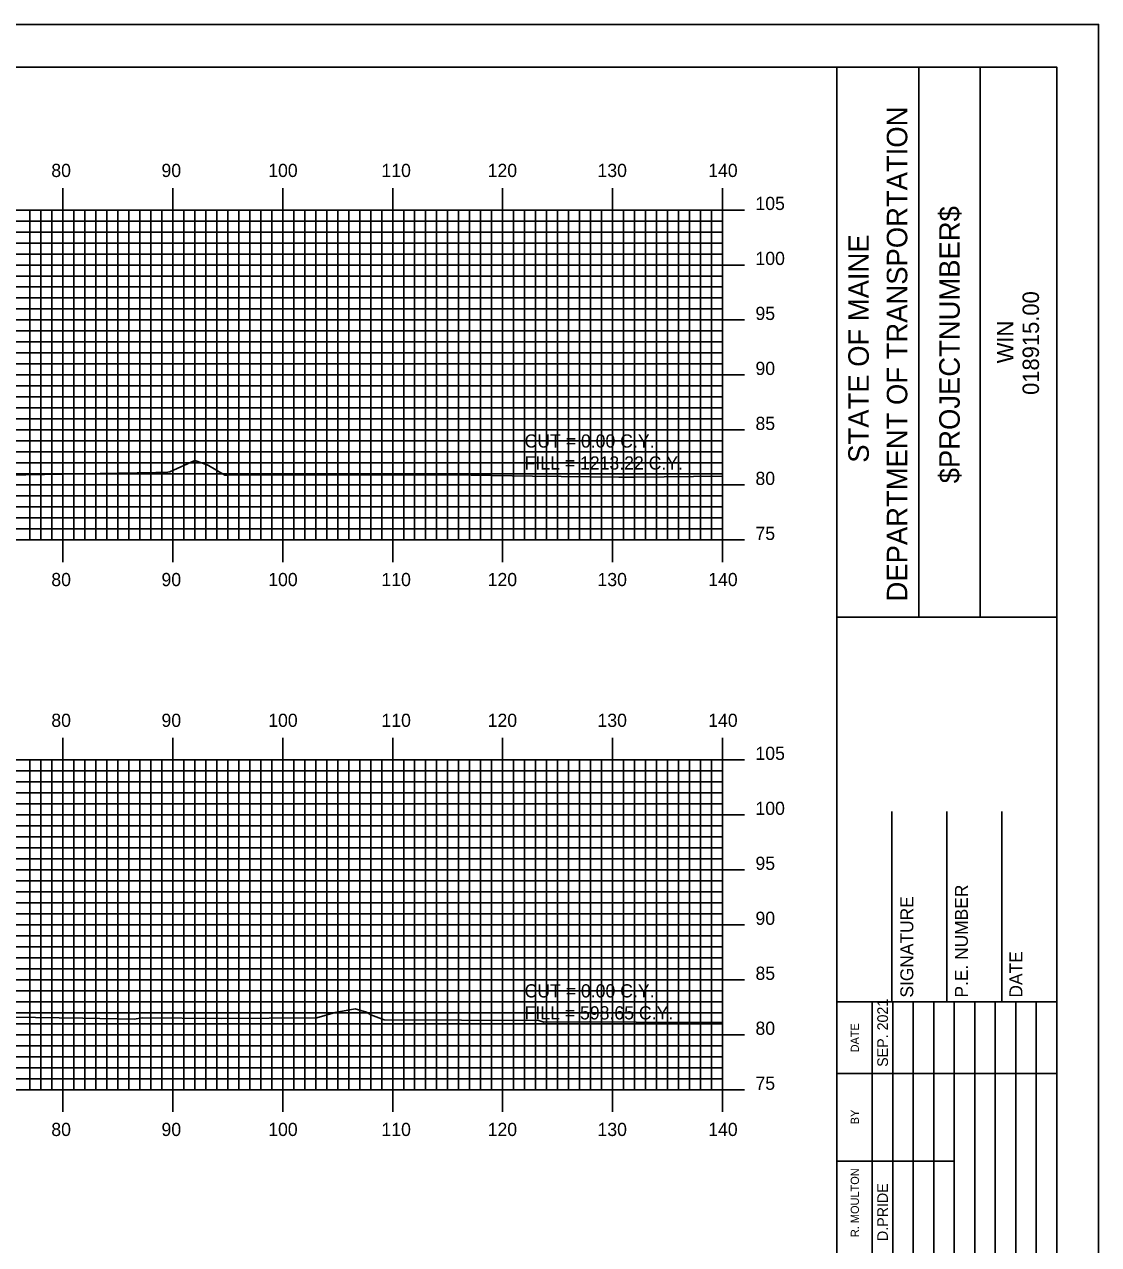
# Model space of a CAD drawing. Extents: x 2453 to 2796, y -1658 to -1438.
# Drawn here: x 2695.2 to 2792.9, y -1548.7 to -1437.7 of the extents above; entities that cross this region are included whole.
import ezdxf

# ---------------------------------------------------------------- set-up
doc = ezdxf.new("R2010")
doc.units = 0
for name, color, linetype in [('BORDER', 7, 'Continuous'), ('D_Text_Standard', 7, 'Continuous'), ('H_V ANNOTATION', 7, 'Continuous'), ('MAJOR', 7, 'Continuous'), ('MINOR', 7, 'Continuous'), ('PLOT BOUNDARY', 7, 'Continuous'), ('S_Roadway_Centerline', 7, 'Continuous')]:
    doc.layers.add(name, color=color, linetype=linetype)

msp = doc.modelspace()

# ---------------------------------------------------------------- linework, layer by layer
at = {"layer": 'BORDER'}
for p, q in [((2769.1, -1651.6), (2769.1, -1441.6)), ((2776.56, -1491.61), (2776.56, -1441.61)), ((2782.15, -1491.61), (2782.15, -1441.61)), ((2769.1, -1491.62), (2789.1, -1491.62)), ((2774.1, -1526.6), (2774.1, -1509.3)), ((2779.1, -1526.6), (2779.1, -1509.3)), ((2784.1, -1526.6), (2784.1, -1509.3)), ((2769.1, -1526.6), (2789.1, -1526.6))]:
    msp.add_line(p, q, dxfattribs=at)
msp.add_lwpolyline([(2469.1, -1651.6), (2789.1, -1651.6), (2789.1, -1441.6), (2469.1, -1441.6)], close=True, dxfattribs=at)
for points in [[(2772.33, -1533.1), (2772.33, -1526.6)], [(2774.19, -1561.59), (2774.19, -1526.6)], [(2776.06, -1526.6), (2776.06, -1561.59)], [(2777.92, -1561.59), (2777.92, -1526.6)], [(2779.78, -1561.59), (2779.78, -1526.6)], [(2781.65, -1561.59), (2781.65, -1526.6)], [(2783.51, -1561.59), (2783.51, -1526.6)], [(2785.37, -1561.59), (2785.37, -1526.6)], [(2787.24, -1561.59), (2787.24, -1526.6)], [(2772.33, -1561.59), (2772.33, -1528.01)], [(2769.1, -1533.1), (2789.1, -1533.1)], [(2769.1, -1541.1), (2772.33, -1541.1)], [(2772.33, -1541.1), (2779.78, -1541.1)]]:
    msp.add_lwpolyline(points, dxfattribs=at)
at = {"layer": 'MAJOR'}
for p, q in [((2698.7, -1452.6), (2698.7, -1454.6)), ((2708.7, -1452.6), (2708.7, -1454.6)), ((2718.7, -1452.6), (2718.7, -1454.6)), ((2728.7, -1452.6), (2728.7, -1454.6)), ((2738.7, -1452.6), (2738.7, -1454.6)), ((2748.7, -1452.6), (2748.7, -1454.6)), ((2758.7, -1452.6), (2758.7, -1454.6)), ((2478.7, -1454.6), (2758.7, -1454.6)), ((2478.7, -1454.6), (2758.7, -1454.6)), ((2698.7, -1484.6), (2698.7, -1454.6)), ((2708.7, -1484.6), (2708.7, -1454.6)), ((2718.7, -1484.6), (2718.7, -1454.6)), ((2728.7, -1484.6), (2728.7, -1454.6)), ((2738.7, -1484.6), (2738.7, -1454.6)), ((2748.7, -1484.6), (2748.7, -1454.6)), ((2760.7, -1454.6), (2756.7, -1454.6)), ((2758.7, -1484.6), (2758.7, -1454.6)), ((2758.7, -1484.6), (2758.7, -1454.6)), ((2478.7, -1459.6), (2758.7, -1459.6)), ((2760.7, -1459.6), (2756.7, -1459.6)), ((2478.7, -1464.6), (2758.7, -1464.6)), ((2760.7, -1464.6), (2756.7, -1464.6)), ((2478.7, -1469.6), (2758.7, -1469.6)), ((2760.7, -1469.6), (2756.7, -1469.6)), ((2478.7, -1474.6), (2758.7, -1474.6)), ((2760.7, -1474.6), (2756.7, -1474.6)), ((2478.7, -1479.6), (2758.7, -1479.6)), ((2760.7, -1479.6), (2756.7, -1479.6)), ((2478.7, -1484.6), (2758.7, -1484.6)), ((2478.7, -1484.6), (2758.7, -1484.6)), ((2698.7, -1486.61), (2698.7, -1484.6)), ((2708.7, -1486.61), (2708.7, -1484.6)), ((2718.7, -1486.61), (2718.7, -1484.6)), ((2728.7, -1486.61), (2728.7, -1484.6)), ((2738.7, -1486.61), (2738.7, -1484.6)), ((2748.7, -1486.61), (2748.7, -1484.6)), ((2760.7, -1484.6), (2756.7, -1484.6)), ((2758.7, -1486.61), (2758.7, -1484.6)), ((2698.7, -1502.6), (2698.7, -1504.6)), ((2708.7, -1502.6), (2708.7, -1504.6)), ((2718.7, -1502.6), (2718.7, -1504.6)), ((2728.7, -1502.6), (2728.7, -1504.6)), ((2738.7, -1502.6), (2738.7, -1504.6)), ((2748.7, -1502.6), (2748.7, -1504.6)), ((2758.7, -1502.6), (2758.7, -1504.6)), ((2478.7, -1504.6), (2758.7, -1504.6)), ((2478.7, -1504.6), (2758.7, -1504.6)), ((2698.7, -1534.6), (2698.7, -1504.6)), ((2708.7, -1534.6), (2708.7, -1504.6)), ((2718.7, -1534.6), (2718.7, -1504.6)), ((2728.7, -1534.6), (2728.7, -1504.6)), ((2738.7, -1534.6), (2738.7, -1504.6)), ((2748.7, -1534.6), (2748.7, -1504.6)), ((2760.7, -1504.6), (2756.7, -1504.6)), ((2758.7, -1534.6), (2758.7, -1504.6)), ((2758.7, -1534.6), (2758.7, -1504.6)), ((2478.7, -1509.6), (2758.7, -1509.6)), ((2760.7, -1509.6), (2756.7, -1509.6)), ((2478.7, -1514.6), (2758.7, -1514.6)), ((2760.7, -1514.6), (2756.7, -1514.6)), ((2478.7, -1519.6), (2758.7, -1519.6)), ((2760.7, -1519.6), (2756.7, -1519.6)), ((2478.7, -1524.6), (2758.7, -1524.6)), ((2760.7, -1524.6), (2756.7, -1524.6)), ((2478.7, -1529.6), (2758.7, -1529.6)), ((2760.7, -1529.6), (2756.7, -1529.6)), ((2478.7, -1534.6), (2758.7, -1534.6)), ((2478.7, -1534.6), (2758.7, -1534.6)), ((2698.7, -1536.61), (2698.7, -1534.6)), ((2708.7, -1536.61), (2708.7, -1534.6)), ((2718.7, -1536.61), (2718.7, -1534.6)), ((2728.7, -1536.61), (2728.7, -1534.6)), ((2738.7, -1536.61), (2738.7, -1534.6)), ((2748.7, -1536.61), (2748.7, -1534.6)), ((2760.7, -1534.6), (2756.7, -1534.6)), ((2758.7, -1536.61), (2758.7, -1534.6))]:
    msp.add_line(p, q, dxfattribs=at)
at = {"layer": 'MINOR'}
for p, q in [((2478.7, -1455.6), (2758.7, -1455.6)), ((2695.7, -1484.6), (2695.7, -1454.6)), ((2696.7, -1484.6), (2696.7, -1454.6)), ((2697.7, -1484.6), (2697.7, -1454.6)), ((2699.7, -1484.6), (2699.7, -1454.6)), ((2700.7, -1484.6), (2700.7, -1454.6)), ((2701.7, -1484.6), (2701.7, -1454.6)), ((2702.7, -1484.6), (2702.7, -1454.6)), ((2703.7, -1484.6), (2703.7, -1454.6)), ((2704.7, -1484.6), (2704.7, -1454.6)), ((2705.7, -1484.6), (2705.7, -1454.6)), ((2706.7, -1484.6), (2706.7, -1454.6)), ((2707.7, -1484.6), (2707.7, -1454.6)), ((2709.7, -1484.6), (2709.7, -1454.6)), ((2710.7, -1484.6), (2710.7, -1454.6)), ((2711.7, -1484.6), (2711.7, -1454.6)), ((2712.7, -1484.6), (2712.7, -1454.6)), ((2713.7, -1484.6), (2713.7, -1454.6)), ((2714.7, -1484.6), (2714.7, -1454.6)), ((2715.7, -1484.6), (2715.7, -1454.6)), ((2716.7, -1484.6), (2716.7, -1454.6)), ((2717.7, -1484.6), (2717.7, -1454.6)), ((2719.7, -1484.6), (2719.7, -1454.6)), ((2720.7, -1484.6), (2720.7, -1454.6)), ((2721.7, -1484.6), (2721.7, -1454.6)), ((2722.7, -1484.6), (2722.7, -1454.6)), ((2723.7, -1484.6), (2723.7, -1454.6)), ((2724.7, -1484.6), (2724.7, -1454.6)), ((2725.7, -1484.6), (2725.7, -1454.6)), ((2726.7, -1484.6), (2726.7, -1454.6)), ((2727.7, -1484.6), (2727.7, -1454.6)), ((2729.7, -1484.6), (2729.7, -1454.6)), ((2730.7, -1484.6), (2730.7, -1454.6)), ((2731.7, -1484.6), (2731.7, -1454.6)), ((2732.7, -1484.6), (2732.7, -1454.6)), ((2733.7, -1484.6), (2733.7, -1454.6)), ((2734.7, -1484.6), (2734.7, -1454.6)), ((2735.7, -1484.6), (2735.7, -1454.6)), ((2736.7, -1484.6), (2736.7, -1454.6)), ((2737.7, -1484.6), (2737.7, -1454.6)), ((2739.7, -1484.6), (2739.7, -1454.6)), ((2740.7, -1484.6), (2740.7, -1454.6)), ((2741.7, -1484.6), (2741.7, -1454.6)), ((2742.7, -1484.6), (2742.7, -1454.6)), ((2743.7, -1484.6), (2743.7, -1454.6)), ((2744.7, -1484.6), (2744.7, -1454.6)), ((2745.7, -1484.6), (2745.7, -1454.6)), ((2746.7, -1484.6), (2746.7, -1454.6)), ((2747.7, -1484.6), (2747.7, -1454.6)), ((2749.7, -1484.6), (2749.7, -1454.6)), ((2750.7, -1484.6), (2750.7, -1454.6)), ((2751.7, -1484.6), (2751.7, -1454.6)), ((2752.7, -1484.6), (2752.7, -1454.6)), ((2753.7, -1484.6), (2753.7, -1454.6)), ((2754.7, -1484.6), (2754.7, -1454.6)), ((2755.7, -1484.6), (2755.7, -1454.6)), ((2756.7, -1484.6), (2756.7, -1454.6)), ((2758.7, -1455.6), (2756.7, -1455.6)), ((2757.7, -1484.6), (2757.7, -1454.6)), ((2478.7, -1456.6), (2758.7, -1456.6)), ((2758.7, -1456.6), (2756.7, -1456.6)), ((2478.7, -1457.6), (2758.7, -1457.6)), ((2758.7, -1457.6), (2756.7, -1457.6)), ((2478.7, -1458.6), (2758.7, -1458.6)), ((2758.7, -1458.6), (2756.7, -1458.6)), ((2478.7, -1460.6), (2758.7, -1460.6)), ((2758.7, -1460.6), (2756.7, -1460.6)), ((2478.7, -1461.6), (2758.7, -1461.6)), ((2758.7, -1461.6), (2756.7, -1461.6)), ((2478.7, -1462.6), (2758.7, -1462.6)), ((2758.7, -1462.6), (2756.7, -1462.6)), ((2478.7, -1463.6), (2758.7, -1463.6)), ((2758.7, -1463.6), (2756.7, -1463.6)), ((2478.7, -1465.6), (2758.7, -1465.6)), ((2758.7, -1465.6), (2756.7, -1465.6)), ((2478.7, -1466.6), (2758.7, -1466.6)), ((2758.7, -1466.6), (2756.7, -1466.6)), ((2478.7, -1467.6), (2758.7, -1467.6)), ((2758.7, -1467.6), (2756.7, -1467.6)), ((2478.7, -1468.6), (2758.7, -1468.6)), ((2758.7, -1468.6), (2756.7, -1468.6)), ((2478.7, -1470.6), (2758.7, -1470.6)), ((2758.7, -1470.6), (2756.7, -1470.6)), ((2478.7, -1471.6), (2758.7, -1471.6)), ((2758.7, -1471.6), (2756.7, -1471.6)), ((2478.7, -1472.6), (2758.7, -1472.6)), ((2758.7, -1472.6), (2756.7, -1472.6)), ((2478.7, -1473.6), (2758.7, -1473.6)), ((2758.7, -1473.6), (2756.7, -1473.6)), ((2478.7, -1475.6), (2758.7, -1475.6)), ((2758.7, -1475.6), (2756.7, -1475.6)), ((2478.7, -1476.6), (2758.7, -1476.6)), ((2758.7, -1476.6), (2756.7, -1476.6)), ((2478.7, -1477.6), (2758.7, -1477.6)), ((2758.7, -1477.6), (2756.7, -1477.6)), ((2478.7, -1478.6), (2758.7, -1478.6)), ((2758.7, -1478.6), (2756.7, -1478.6)), ((2478.7, -1480.6), (2758.7, -1480.6)), ((2758.7, -1480.6), (2756.7, -1480.6)), ((2478.7, -1481.6), (2758.7, -1481.6)), ((2758.7, -1481.6), (2756.7, -1481.6)), ((2478.7, -1482.6), (2758.7, -1482.6)), ((2758.7, -1482.6), (2756.7, -1482.6)), ((2478.7, -1483.6), (2758.7, -1483.6)), ((2758.7, -1483.6), (2756.7, -1483.6)), ((2695.7, -1534.6), (2695.7, -1504.6)), ((2696.7, -1534.6), (2696.7, -1504.6)), ((2697.7, -1534.6), (2697.7, -1504.6)), ((2699.7, -1534.6), (2699.7, -1504.6)), ((2700.7, -1534.6), (2700.7, -1504.6)), ((2701.7, -1534.6), (2701.7, -1504.6)), ((2702.7, -1534.6), (2702.7, -1504.6)), ((2703.7, -1534.6), (2703.7, -1504.6)), ((2704.7, -1534.6), (2704.7, -1504.6)), ((2705.7, -1534.6), (2705.7, -1504.6)), ((2706.7, -1534.6), (2706.7, -1504.6)), ((2707.7, -1534.6), (2707.7, -1504.6)), ((2709.7, -1534.6), (2709.7, -1504.6)), ((2710.7, -1534.6), (2710.7, -1504.6)), ((2711.7, -1534.6), (2711.7, -1504.6)), ((2712.7, -1534.6), (2712.7, -1504.6)), ((2713.7, -1534.6), (2713.7, -1504.6)), ((2714.7, -1534.6), (2714.7, -1504.6)), ((2715.7, -1534.6), (2715.7, -1504.6)), ((2716.7, -1534.6), (2716.7, -1504.6)), ((2717.7, -1534.6), (2717.7, -1504.6)), ((2719.7, -1534.6), (2719.7, -1504.6)), ((2720.7, -1534.6), (2720.7, -1504.6)), ((2721.7, -1534.6), (2721.7, -1504.6)), ((2722.7, -1534.6), (2722.7, -1504.6)), ((2723.7, -1534.6), (2723.7, -1504.6)), ((2724.7, -1534.6), (2724.7, -1504.6)), ((2725.7, -1534.6), (2725.7, -1504.6)), ((2726.7, -1534.6), (2726.7, -1504.6)), ((2727.7, -1534.6), (2727.7, -1504.6)), ((2729.7, -1534.6), (2729.7, -1504.6)), ((2730.7, -1534.6), (2730.7, -1504.6)), ((2731.7, -1534.6), (2731.7, -1504.6)), ((2732.7, -1534.6), (2732.7, -1504.6)), ((2733.7, -1534.6), (2733.7, -1504.6)), ((2734.7, -1534.6), (2734.7, -1504.6)), ((2735.7, -1534.6), (2735.7, -1504.6)), ((2736.7, -1534.6), (2736.7, -1504.6)), ((2737.7, -1534.6), (2737.7, -1504.6)), ((2739.7, -1534.6), (2739.7, -1504.6)), ((2740.7, -1534.6), (2740.7, -1504.6)), ((2741.7, -1534.6), (2741.7, -1504.6)), ((2742.7, -1534.6), (2742.7, -1504.6)), ((2743.7, -1534.6), (2743.7, -1504.6)), ((2744.7, -1534.6), (2744.7, -1504.6)), ((2745.7, -1534.6), (2745.7, -1504.6)), ((2746.7, -1534.6), (2746.7, -1504.6)), ((2747.7, -1534.6), (2747.7, -1504.6)), ((2749.7, -1534.6), (2749.7, -1504.6)), ((2750.7, -1534.6), (2750.7, -1504.6)), ((2751.7, -1534.6), (2751.7, -1504.6)), ((2752.7, -1534.6), (2752.7, -1504.6)), ((2753.7, -1534.6), (2753.7, -1504.6)), ((2754.7, -1534.6), (2754.7, -1504.6)), ((2755.7, -1534.6), (2755.7, -1504.6)), ((2756.7, -1534.6), (2756.7, -1504.6)), ((2757.7, -1534.6), (2757.7, -1504.6)), ((2478.7, -1505.6), (2758.7, -1505.6)), ((2478.7, -1506.6), (2758.7, -1506.6)), ((2758.7, -1505.6), (2756.7, -1505.6)), ((2758.7, -1506.6), (2756.7, -1506.6)), ((2478.7, -1507.6), (2758.7, -1507.6)), ((2758.7, -1507.6), (2756.7, -1507.6)), ((2478.7, -1508.6), (2758.7, -1508.6)), ((2758.7, -1508.6), (2756.7, -1508.6)), ((2478.7, -1510.6), (2758.7, -1510.6)), ((2758.7, -1510.6), (2756.7, -1510.6)), ((2478.7, -1511.6), (2758.7, -1511.6)), ((2758.7, -1511.6), (2756.7, -1511.6)), ((2478.7, -1512.6), (2758.7, -1512.6)), ((2758.7, -1512.6), (2756.7, -1512.6)), ((2478.7, -1513.6), (2758.7, -1513.6)), ((2758.7, -1513.6), (2756.7, -1513.6)), ((2478.7, -1515.6), (2758.7, -1515.6)), ((2478.7, -1516.6), (2758.7, -1516.6)), ((2758.7, -1515.6), (2756.7, -1515.6)), ((2758.7, -1516.6), (2756.7, -1516.6)), ((2478.7, -1517.6), (2758.7, -1517.6)), ((2758.7, -1517.6), (2756.7, -1517.6)), ((2478.7, -1518.6), (2758.7, -1518.6)), ((2758.7, -1518.6), (2756.7, -1518.6)), ((2478.7, -1520.6), (2758.7, -1520.6)), ((2758.7, -1520.6), (2756.7, -1520.6)), ((2478.7, -1521.6), (2758.7, -1521.6)), ((2758.7, -1521.6), (2756.7, -1521.6)), ((2478.7, -1522.6), (2758.7, -1522.6)), ((2758.7, -1522.6), (2756.7, -1522.6)), ((2478.7, -1523.6), (2758.7, -1523.6)), ((2758.7, -1523.6), (2756.7, -1523.6)), ((2478.7, -1525.6), (2758.7, -1525.6)), ((2478.7, -1526.6), (2758.7, -1526.6)), ((2758.7, -1525.6), (2756.7, -1525.6)), ((2758.7, -1526.6), (2756.7, -1526.6)), ((2478.7, -1527.6), (2758.7, -1527.6)), ((2758.7, -1527.6), (2756.7, -1527.6)), ((2478.7, -1528.6), (2758.7, -1528.6)), ((2758.7, -1528.6), (2756.7, -1528.6)), ((2478.7, -1530.6), (2758.7, -1530.6)), ((2758.7, -1530.6), (2756.7, -1530.6)), ((2478.7, -1531.6), (2758.7, -1531.6)), ((2758.7, -1531.6), (2756.7, -1531.6)), ((2478.7, -1532.6), (2758.7, -1532.6)), ((2758.7, -1532.6), (2756.7, -1532.6)), ((2478.7, -1533.6), (2758.7, -1533.6)), ((2758.7, -1533.6), (2756.7, -1533.6))]:
    msp.add_line(p, q, dxfattribs=at)
at = {"layer": 'PLOT BOUNDARY'}
msp.add_lwpolyline([(2452.91, -1657.72), (2792.91, -1657.72), (2792.91, -1437.72), (2452.91, -1437.72)], close=True, dxfattribs=at)
at = {"layer": 'S_Roadway_Centerline'}
for points in [[(2690.23, -1478.77), (2707.16, -1478.46), (2708.24, -1478.45), (2708.44, -1478.41), (2710.69, -1477.37), (2711.84, -1477.77), (2711.95, -1477.84), (2713.43, -1478.7), (2713.69, -1478.7), (2733.56, -1478.67), (2733.98, -1478.68), (2741.41, -1478.79), (2749.27, -1478.9), (2750.77, -1478.88), (2758.7, -1478.81)], [(2687.56, -1527.91), (2700.51, -1528.07), (2705.2, -1528.17), (2705.95, -1528.04), (2713.12, -1528.1), (2721.79, -1528.06), (2723.48, -1527.58), (2725.29, -1527.23), (2726.32, -1527.54), (2726.7, -1527.78), (2727.93, -1528.25), (2742, -1528.31), (2742.45, -1528.46), (2746.58, -1528.41), (2755.11, -1528.47), (2758.7, -1528.46)]]:
    msp.add_lwpolyline(points, dxfattribs=at)

# ---------------------------------------------------------------- texts
at = {"layer": 'BORDER'}
for s, height, p in [('DEPARTMENT OF TRANSPORTATION', 1.8635, (2775.51, -1490.19)), ('$PROJECTNUMBER$', 1.8635, (2780.28, -1479.45)), ('STATE OF MAINE', 1.8635, (2772.01, -1477.58)), ('018915.00', 1.491, (2787.49, -1471.41)), ('WIN', 1.491, (2785.17, -1468.54)), ('P.E. NUMBER', 1.1811, (2781.02, -1526.21)), ('SIGNATURE', 1.181, (2776.06, -1526.21)), ('DATE', 1.181, (2785.98, -1526.21)), ('SEP. 2021', 0.969, (2773.75, -1532.51)), ('DATE', 0.743, (2771.11, -1531.19)), ('BY', 0.743, (2771.11, -1537.73)), ('R. MOULTON', 0.745, (2771.11, -1547.99)), ('D.PRIDE', 0.969, (2773.75, -1548.35))]:
    msp.add_text(s, height=height, rotation=90, dxfattribs=at).set_placement(p)
at = {"layer": 'D_Text_Standard'}
for s, p in [('CUT = 0.00 C.Y.', (2740.7, -1476.2)), ('FILL = 1213.22 C.Y.', (2740.7, -1478.2)), ('CUT = 0.00 C.Y.', (2740.7, -1526.2)), ('FILL = 598.65 C.Y.', (2740.7, -1528.2))]:
    msp.add_text(s, height=1.2, dxfattribs=at).set_placement(p)
at = {"layer": 'H_V ANNOTATION'}
for s, p in [('80', (2697.65, -1451.6)), ('90', (2707.67, -1451.6)), ('100', (2717.38, -1451.6)), ('110', (2727.68, -1451.6)), ('120', (2737.34, -1451.6)), ('130', (2747.33, -1451.6)), ('140', (2757.4, -1451.6)), ('105', (2761.7, -1454.6)), ('100', (2761.7, -1459.6)), ('95', (2761.7, -1464.6)), ('90', (2761.7, -1469.6)), ('85', (2761.7, -1474.6)), ('80', (2761.7, -1479.6)), ('75', (2761.7, -1484.6)), ('80', (2697.65, -1488.8)), ('90', (2707.67, -1488.8)), ('100', (2717.38, -1488.8)), ('110', (2727.68, -1488.8)), ('120', (2737.34, -1488.8)), ('130', (2747.33, -1488.8)), ('140', (2757.4, -1488.8)), ('80', (2697.65, -1501.6)), ('90', (2707.67, -1501.6)), ('100', (2717.38, -1501.6)), ('110', (2727.68, -1501.6)), ('120', (2737.34, -1501.6)), ('130', (2747.33, -1501.6)), ('140', (2757.4, -1501.6)), ('105', (2761.7, -1504.6)), ('100', (2761.7, -1509.6)), ('95', (2761.7, -1514.6)), ('90', (2761.7, -1519.6)), ('85', (2761.7, -1524.6)), ('80', (2761.7, -1529.6)), ('75', (2761.7, -1534.6)), ('80', (2697.65, -1538.8)), ('90', (2707.67, -1538.8)), ('100', (2717.38, -1538.8)), ('110', (2727.68, -1538.8)), ('120', (2737.34, -1538.8)), ('130', (2747.33, -1538.8)), ('140', (2757.4, -1538.8))]:
    msp.add_text(s, height=1.2, dxfattribs=at).set_placement(p)

doc.saveas('drawing.dxf')
